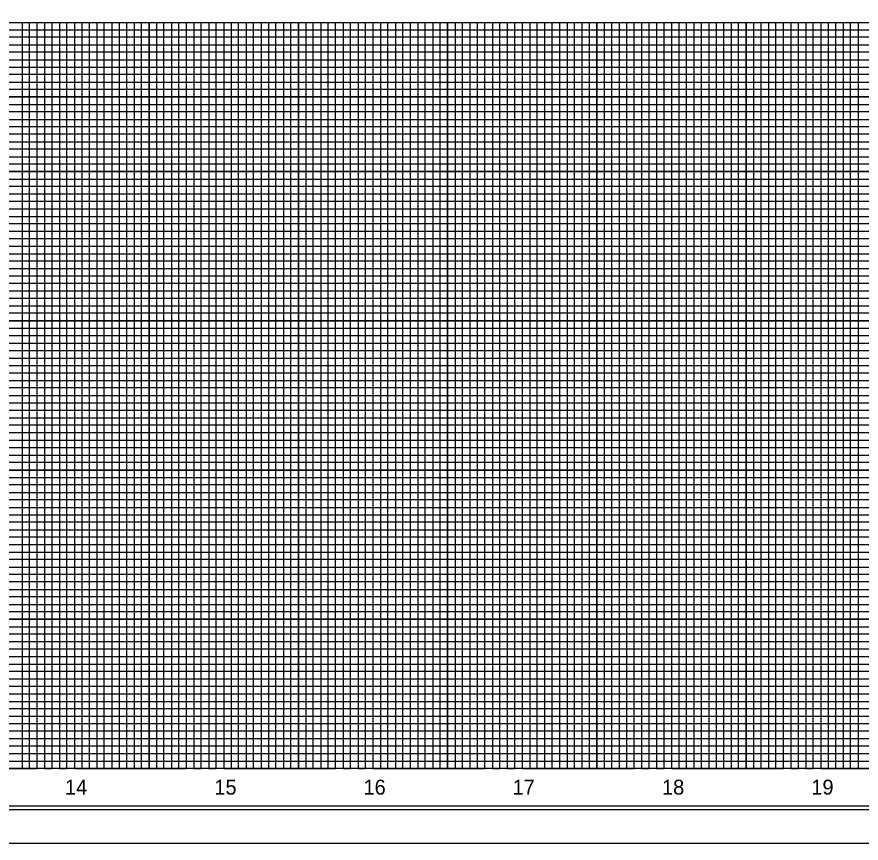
# Model space of a CAD drawing. Extents: x 2186391 to 2188300, y 74582 to 75682.
# Drawn here: x 2186969 to 2187535, y 74582 to 75136 of the extents above; entities that cross this region are included whole.
import ezdxf

# ---------------------------------------------------------------- set-up
doc = ezdxf.new("R2010")
doc.units = 0
for name, color, linetype in [('Old_Level_1', 7, 'Continuous'), ('Old_Level_11', 7, 'Continuous'), ('Old_Level_2', 7, 'Continuous'), ('Scratch_Level_0', 7, 'Continuous'), ('Sheet Border Standard 30in CELL', 7, 'Continuous'), ('Sheet Cutting Line CELL', 7, 'Continuous'), ('Sheet Plot Border Outside CELL', 7, 'Continuous'), ('Sheet Sticker Exception Certification CELL', 7, 'Continuous'), ('Sheet Sticker Incomplete CELL', 7, 'Continuous'), ('Sheet Sticker Preliminary CELL', 7, 'Continuous')]:
    doc.layers.add(name, color=color, linetype=linetype)

msp = doc.modelspace()

# ---------------------------------------------------------------- linework, layer by layer
at = {"layer": 'Old_Level_11'}
for p, q in [((2186557.69, 75132.28), (2188057.58, 75132.28)), ((2187007.69, 75132.28), (2187007.69, 74632.28)), ((2187057.69, 75132.28), (2187057.69, 74632.28)), ((2187107.69, 75132.28), (2187107.69, 74632.28)), ((2187157.69, 75132.28), (2187157.69, 74632.28)), ((2187207.69, 75132.28), (2187207.69, 74632.28)), ((2187257.69, 75132.28), (2187257.69, 74632.28)), ((2187307.69, 75132.28), (2187307.69, 74632.28)), ((2187357.69, 75132.28), (2187357.69, 74632.28)), ((2187407.69, 75132.28), (2187407.69, 74632.28)), ((2187457.69, 75132.28), (2187457.69, 74632.28)), ((2187507.69, 75132.28), (2187507.69, 74632.28)), ((2186557.69, 75082.28), (2188057.58, 75082.28)), ((2186557.69, 75032.28), (2188057.58, 75032.28)), ((2186557.69, 74982.28), (2188057.58, 74982.28)), ((2186557.69, 74932.28), (2188057.58, 74932.28)), ((2186557.69, 74882.28), (2188057.58, 74882.28)), ((2186557.69, 74832.28), (2188057.58, 74832.28)), ((2186557.69, 74782.28), (2188057.58, 74782.28)), ((2186557.69, 74732.28), (2188057.58, 74732.28)), ((2186557.69, 74682.28), (2188057.58, 74682.28))]:
    msp.add_line(p, q, dxfattribs=at)
at = {"layer": 'Old_Level_2'}
for points in [[(2186932.69, 74632.28), (2186982.69, 74632.28), (2186982.69, 75132.28), (2187032.69, 75132.28), (2187032.69, 74632.28), (2187082.69, 74632.28), (2187082.69, 75132.28), (2187132.69, 75132.28), (2187132.69, 74632.28), (2187182.69, 74632.28), (2187182.69, 74632.28), (2187182.69, 75132.28), (2187232.69, 75132.28), (2187232.69, 74632.28), (2187282.69, 74632.28), (2187282.69, 75132.28), (2187332.69, 75132.28), (2187332.69, 74632.28), (2187382.69, 74632.28), (2187382.69, 75132.28), (2187432.69, 75132.28), (2187432.69, 74632.28), (2187482.69, 74632.28), (2187482.69, 75132.28), (2187532.69, 75132.28), (2187532.69, 74632.28), (2187582.69, 74632.28)], [(2186557.69, 75107.28), (2188057.69, 75107.28)], [(2188057.69, 75057.28), (2186557.69, 75057.28), (2186557.69, 75007.28), (2188057.69, 75007.28)], [(2188057.69, 74957.28), (2186557.69, 74957.28), (2186557.69, 74907.28), (2188057.69, 74907.28)], [(2188057.69, 74857.28), (2186557.69, 74857.28), (2186557.69, 74807.28), (2188057.69, 74807.28)], [(2188057.69, 74757.28), (2186557.69, 74757.28), (2186557.69, 74707.28), (2188057.69, 74707.28)], [(2188057.69, 74657.28), (2186557.69, 74657.28)]]:
    msp.add_lwpolyline(points, dxfattribs=at)
at = {"layer": 'Scratch_Level_0'}
msp.add_line((2186390.69, 74582.28), (2188074.69, 74582.28), dxfattribs=at)
at = {"layer": 'Sheet Border Standard 30in CELL'}
msp.add_lwpolyline([(2186607.69, 75132.28), (2188007.69, 75132.28), (2188007.69, 74632.28), (2186607.69, 74632.28)], close=True, dxfattribs=at)
msp.add_lwpolyline([(2186607.69, 75132.28), (2188007.69, 75132.28), (2188007.69, 74632.28), (2186607.69, 74632.28)], close=True, dxfattribs=at)
at = {"layer": 'Sheet Cutting Line CELL'}
for p, q in [((2186557.69, 75132.28), (2188057.69, 75132.28)), ((2188057.69, 74632.28), (2186557.69, 74632.28)), ((2186557.69, 74607.28), (2188057.69, 74607.28))]:
    msp.add_line(p, q, dxfattribs=at)
msp.add_lwpolyline([(2188057.69, 75657.28), (2186557.69, 75657.28), (2186557.69, 74607.28), (2188057.69, 74607.28)], close=True, dxfattribs=at)
at = {"layer": 'Sheet Plot Border Outside CELL'}
for p, q in [((2186607.69, 75127.28), (2188007.69, 75127.28)), ((2188007.69, 75122.28), (2186607.69, 75122.28)), ((2186607.69, 75117.28), (2188007.69, 75117.28)), ((2188007.69, 75112.28), (2186607.69, 75112.28)), ((2186607.69, 75102.28), (2188007.69, 75102.28)), ((2188007.69, 75097.28), (2186607.69, 75097.28)), ((2186607.69, 75092.28), (2188007.69, 75092.28)), ((2188007.69, 75087.28), (2186607.69, 75087.28)), ((2186607.69, 75077.28), (2188007.69, 75077.28)), ((2188007.69, 75072.28), (2186607.69, 75072.28)), ((2186607.69, 75067.28), (2188007.69, 75067.28)), ((2188007.69, 75062.28), (2186607.69, 75062.28)), ((2186607.69, 75052.28), (2188007.69, 75052.28)), ((2188007.69, 75047.28), (2186607.69, 75047.28)), ((2186607.69, 75042.28), (2188007.69, 75042.28)), ((2188007.69, 75037.28), (2186607.69, 75037.28)), ((2186607.69, 75027.28), (2188007.69, 75027.28)), ((2188007.69, 75022.28), (2186607.69, 75022.28)), ((2186607.69, 75017.28), (2188007.69, 75017.28)), ((2188007.69, 75012.28), (2186607.69, 75012.28)), ((2186607.69, 75002.28), (2188007.69, 75002.28)), ((2188007.69, 74997.28), (2186607.69, 74997.28)), ((2186607.69, 74992.28), (2188007.69, 74992.28)), ((2188007.69, 74987.28), (2186607.69, 74987.28)), ((2186607.69, 74977.28), (2188007.69, 74977.28)), ((2188007.69, 74972.28), (2186607.69, 74972.28)), ((2186607.69, 74967.28), (2188007.69, 74967.28)), ((2188007.69, 74962.28), (2186607.69, 74962.28)), ((2186607.69, 74952.28), (2188007.69, 74952.28)), ((2188007.69, 74947.28), (2186607.69, 74947.28)), ((2186607.69, 74942.28), (2188007.69, 74942.28)), ((2188007.69, 74937.28), (2186607.69, 74937.43)), ((2186607.69, 74927.28), (2188007.69, 74927.28)), ((2188007.69, 74922.28), (2186607.69, 74922.28)), ((2186607.69, 74917.28), (2188007.69, 74917.28)), ((2188007.69, 74912.28), (2186607.69, 74912.28)), ((2186607.69, 74902.28), (2188007.69, 74902.28)), ((2188007.69, 74897.28), (2186607.69, 74897.28)), ((2186607.69, 74892.28), (2188007.69, 74892.28)), ((2188007.69, 74887.28), (2186607.69, 74887.28)), ((2186607.69, 74877.28), (2188007.69, 74877.28)), ((2188007.69, 74872.28), (2186607.69, 74872.28)), ((2186607.69, 74867.28), (2188007.69, 74867.28)), ((2188007.69, 74862.28), (2186607.69, 74862.28)), ((2186607.69, 74852.28), (2188007.69, 74852.28)), ((2188007.69, 74847.28), (2186607.69, 74847.28)), ((2186607.69, 74842.28), (2188007.69, 74842.28)), ((2188007.69, 74837.28), (2186607.69, 74837.28)), ((2186607.69, 74827.28), (2188007.69, 74827.28)), ((2188007.69, 74822.28), (2186607.69, 74822.28)), ((2186607.69, 74817.28), (2188007.69, 74817.28)), ((2188007.69, 74812.28), (2186607.69, 74812.28)), ((2186607.69, 74802.28), (2188007.69, 74802.28)), ((2188007.69, 74797.28), (2186607.69, 74797.28)), ((2186607.69, 74792.28), (2188007.69, 74792.28)), ((2188007.69, 74787.28), (2186607.69, 74787.28)), ((2186607.69, 74777.28), (2188007.69, 74777.28)), ((2188007.69, 74772.28), (2186607.69, 74772.28)), ((2186607.69, 74767.28), (2188007.69, 74767.28)), ((2188007.69, 74762.28), (2186607.69, 74762.28)), ((2186607.69, 74752.28), (2188007.69, 74752.28)), ((2188007.69, 74747.28), (2186607.69, 74747.28)), ((2186607.69, 74742.28), (2188007.69, 74742.28)), ((2188007.69, 74737.28), (2186607.69, 74737.28)), ((2186607.69, 74727.28), (2188007.69, 74727.28)), ((2188007.69, 74722.28), (2186607.69, 74722.28)), ((2186607.69, 74717.28), (2188007.69, 74717.28)), ((2188007.69, 74712.28), (2186607.69, 74712.28)), ((2186607.69, 74702.28), (2188007.69, 74702.28)), ((2188007.69, 74697.28), (2186607.69, 74697.28)), ((2186607.69, 74692.28), (2188007.69, 74692.28)), ((2188007.69, 74687.28), (2186607.69, 74687.28)), ((2186607.69, 74677.28), (2188007.69, 74677.28)), ((2188007.69, 74672.28), (2186607.69, 74672.28)), ((2186607.69, 74667.28), (2188007.69, 74667.28)), ((2188007.69, 74662.28), (2186607.69, 74662.28)), ((2186607.69, 74652.28), (2188007.69, 74652.28)), ((2188007.69, 74647.28), (2186607.69, 74647.28)), ((2186607.69, 74642.28), (2188007.69, 74642.28)), ((2186607.69, 74637.28), (2188007.69, 74637.28))]:
    msp.add_line(p, q, dxfattribs=at)
for points in [[(2186967.69, 75132.28), (2186972.69, 75132.28), (2186972.69, 74632.28), (2186977.69, 74632.28), (2186977.69, 75132.28), (2186987.69, 75132.28), (2186987.69, 74632.28), (2186992.69, 74632.28), (2186992.69, 75132.28), (2186997.69, 75132.28), (2186997.69, 74632.28), (2187002.69, 74632.28), (2187002.69, 75132.28), (2187012.69, 75132.28), (2187012.69, 74632.28), (2187017.69, 74632.28), (2187017.69, 75132.28), (2187022.69, 75132.28), (2187022.69, 74632.28), (2187027.69, 74632.28), (2187027.69, 75132.28), (2187037.69, 75132.28), (2187037.69, 74632.28), (2187042.69, 74632.28), (2187042.69, 75132.28), (2187047.69, 75132.28), (2187047.69, 74632.28), (2187052.69, 74632.28), (2187052.69, 75132.28), (2187062.69, 75132.28), (2187062.69, 74632.28), (2187067.69, 74632.28), (2187067.69, 75132.28), (2187072.69, 75132.28), (2187072.69, 74632.28), (2187077.69, 74632.28), (2187077.69, 75132.28), (2187087.69, 75132.28), (2187087.69, 74632.28), (2187092.69, 74632.28), (2187092.69, 75132.28), (2187097.69, 75132.28), (2187097.69, 74632.28), (2187102.69, 74632.28), (2187102.69, 75132.28), (2187112.69, 75132.28), (2187112.69, 74632.28), (2187117.69, 74632.28), (2187117.69, 75132.28), (2187122.69, 75132.28), (2187122.69, 74632.28), (2187127.69, 74632.28), (2187127.69, 75132.28), (2187137.69, 75132.28)], [(2187137.69, 75132.28), (2187137.69, 74632.28), (2187142.69, 74632.28), (2187142.69, 75132.28), (2187147.69, 75132.28), (2187147.69, 74632.28), (2187152.69, 74632.28), (2187152.69, 75132.28), (2187162.69, 75132.28), (2187162.69, 74632.28), (2187167.69, 74632.28), (2187167.69, 75132.28), (2187172.69, 75132.28), (2187172.69, 74632.28), (2187177.69, 74632.28), (2187177.69, 75132.28), (2187187.69, 75132.28), (2187187.69, 74632.28), (2187192.69, 74632.28), (2187192.69, 75132.28), (2187197.69, 75132.28), (2187197.69, 74632.28), (2187202.69, 74632.28), (2187202.69, 75132.28), (2187212.69, 75132.28), (2187212.69, 74632.28), (2187217.69, 74632.28), (2187217.69, 75132.28), (2187222.69, 75132.28), (2187222.69, 74632.28), (2187227.69, 74632.28), (2187227.69, 75132.28), (2187237.69, 75132.28), (2187237.69, 74632.28), (2187242.69, 74632.28), (2187242.69, 75132.28), (2187247.69, 75132.28), (2187247.69, 74632.28), (2187252.69, 74632.28), (2187252.69, 75132.28), (2187262.69, 75132.28), (2187262.69, 74632.28), (2187262.69, 74632.28), (2187267.69, 74632.28), (2187267.69, 75132.28), (2187272.69, 75132.28), (2187272.69, 74632.28), (2187277.69, 74632.28), (2187277.69, 75132.28), (2187287.69, 75132.28), (2187287.69, 74632.28), (2187292.69, 74632.28), (2187292.69, 75132.28), (2187297.69, 75132.28), (2187297.69, 74632.28), (2187302.69, 74632.28), (2187302.69, 75132.28), (2187312.69, 75132.28), (2187312.69, 74632.28), (2187317.69, 74632.28), (2187317.69, 75132.28), (2187322.69, 75132.28), (2187322.69, 74632.28), (2187327.69, 74632.28), (2187327.69, 75132.28), (2187337.69, 75132.28), (2187337.69, 74632.28), (2187342.69, 74632.28), (2187342.69, 75132.28), (2187347.69, 75132.28), (2187347.69, 74632.28), (2187352.69, 74632.28), (2187352.69, 75132.28), (2187362.69, 75132.28), (2187362.69, 74632.28), (2187367.69, 74632.28), (2187367.69, 75132.28), (2187372.69, 75132.28), (2187372.69, 74632.28), (2187377.69, 74632.28), (2187377.69, 75132.28), (2187387.69, 75132.28), (2187387.69, 74632.28), (2187392.69, 74632.28), (2187392.69, 75132.28), (2187397.69, 75132.28), (2187397.69, 74632.28), (2187402.69, 74632.28), (2187402.69, 75132.28), (2187412.69, 75132.28), (2187412.69, 74632.28), (2187417.39, 74632.83), (2187417.69, 74632.28), (2187417.69, 75132.28), (2187422.69, 75132.28), (2187422.69, 74632.28), (2187427.69, 74632.28), (2187427.69, 75132.28), (2187437.69, 75132.28), (2187437.69, 74632.28), (2187442.69, 74632.28)], [(2187442.69, 74632.28), (2187442.69, 75132.28), (2187447.69, 75132.28), (2187447.69, 74632.28), (2187452.69, 74632.28), (2187452.69, 75132.28), (2187462.69, 75132.28), (2187462.69, 74632.28), (2187467.69, 74632.28), (2187467.69, 75132.28), (2187472.69, 75132.28), (2187472.69, 74632.28), (2187477.69, 74632.28), (2187477.69, 75132.28), (2187487.69, 75132.28), (2187487.69, 74632.28), (2187492.69, 74632.28), (2187492.69, 75132.28), (2187497.69, 75132.28), (2187497.69, 74632.28), (2187502.69, 74632.28), (2187502.69, 75132.28), (2187512.69, 75132.28), (2187512.69, 74632.28), (2187517.69, 74632.28), (2187517.69, 75132.28), (2187522.69, 75132.28), (2187522.69, 74632.28), (2187527.69, 74632.28), (2187527.69, 75132.28), (2187537.69, 75132.28)]]:
    msp.add_lwpolyline(points, dxfattribs=at)
at = {"layer": 'Sheet Sticker Exception Certification CELL'}
for p, q in [((2187057.69, 75132.28), (2187107.69, 75132.28)), ((2187157.69, 75132.28), (2187207.69, 75132.28)), ((2187257.69, 75132.28), (2187307.69, 75132.28)), ((2187357.69, 75132.28), (2187407.69, 75132.28)), ((2187457.69, 75132.28), (2187507.69, 75132.28))]:
    msp.add_line(p, q, dxfattribs=at)
for points in [[(2186957.69, 75132.28), (2187007.69, 75132.28), (2187007.69, 74632.28), (2187057.69, 74632.28), (2187057.69, 75132.28), (2187107.69, 75132.28), (2187107.69, 74632.28), (2187157.69, 74632.28), (2187157.69, 75132.28), (2187207.69, 75132.28), (2187207.69, 74632.28), (2187257.69, 74632.28), (2187257.69, 75132.28), (2187307.69, 75132.28), (2187307.69, 74632.28), (2187357.69, 74632.28), (2187357.69, 75132.28), (2187407.69, 75132.28), (2187407.69, 74632.28), (2187457.69, 74632.28), (2187457.69, 75132.28), (2187507.69, 75132.28), (2187507.69, 74632.28), (2187557.69, 74632.28)], [(2188057.69, 75082.28), (2186557.69, 75082.28)], [(2188057.69, 75032.28), (2186557.69, 75032.28), (2186557.69, 74982.28), (2188057.69, 74982.28)], [(2188057.69, 74932.28), (2186557.69, 74932.28), (2186557.69, 74882.28), (2188057.69, 74882.28)], [(2188057.69, 74832.28), (2186557.69, 74832.28), (2186557.69, 74782.28), (2188057.69, 74782.28)], [(2188057.69, 74732.28), (2186557.69, 74732.28), (2186557.69, 74732.28), (2186557.69, 74682.28), (2188057.69, 74682.28)], [(2188057.69, 74632.28), (2186557.69, 74632.28)]]:
    msp.add_lwpolyline(points, dxfattribs=at)
at = {"layer": 'Sheet Sticker Incomplete CELL'}
msp.add_lwpolyline([(2186390.69, 74582.28), (2188074.69, 74582.28), (2188074.69, 75682.28), (2186390.69, 75682.28)], close=True, dxfattribs=at)
at = {"layer": 'Sheet Sticker Preliminary CELL'}
msp.add_lwpolyline([(2186403.69, 74604.73), (2188070.19, 74604.73), (2188070.19, 75659.83), (2186403.69, 75659.83)], close=True, dxfattribs=at)

# ---------------------------------------------------------------- texts
at = {"layer": 'Old_Level_1'}
for s, p in [('14', (2187001.34, 74614.78)), ('15', (2187101.43, 74614.78)), ('16', (2187201.37, 74614.78)), ('17', (2187301.23, 74614.78)), ('18', (2187401.35, 74614.78)), ('19', (2187501.4, 74614.78))]:
    msp.add_text(s, height=10, dxfattribs=at).set_placement(p)

doc.saveas('drawing.dxf')
